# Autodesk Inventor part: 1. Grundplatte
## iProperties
Created: 2011-05
Part Number: 1. Grundplatte
Document SubType Name: Modeling
Designer: Lorenz Humpel
Density: 1 g/cm^3
Author: Lorenz Humpel
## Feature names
1. Extrusion1
